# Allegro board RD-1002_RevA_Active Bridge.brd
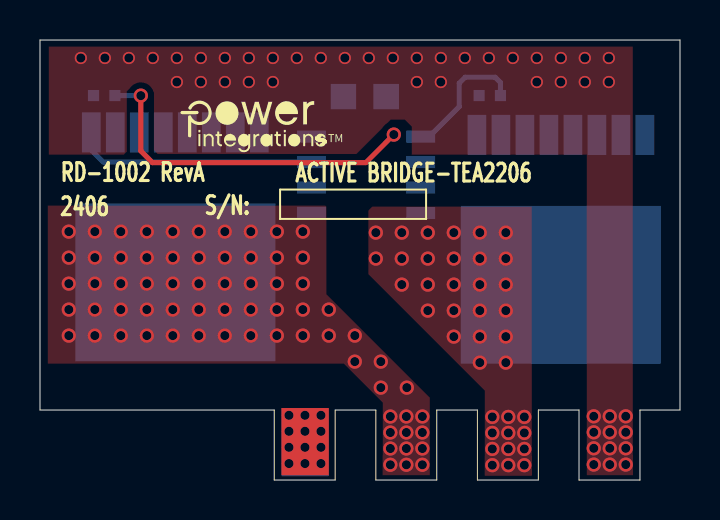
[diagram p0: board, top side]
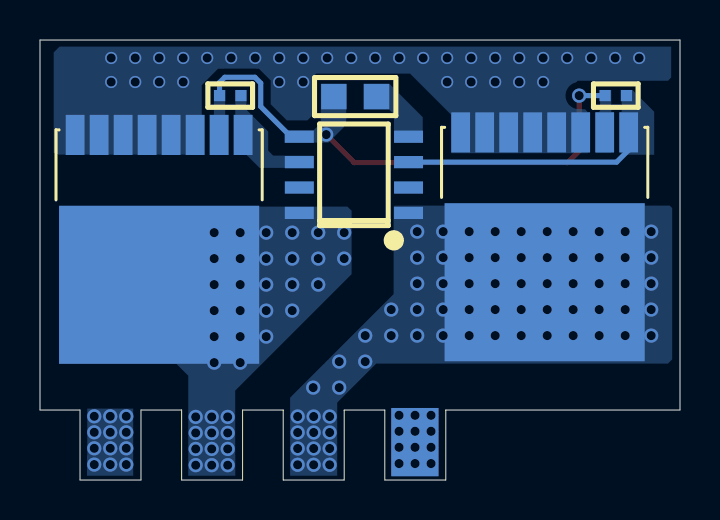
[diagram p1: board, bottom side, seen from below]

Outline 32 x 22 mm; copper layers: TOP, BOTTOM. Coordinates in mm from the lower left corner of the outline.
Outline path: 0,22 0,3.5 11.71,3.5 11.71,0 14.76,0 14.76,3.5 16.79,3.5 16.79,0 19.84,0 19.84,3.5 21.87,3.5 21.87,0 24.92,0 24.92,3.5 26.95,3.5 26.95,0 30,0 30,3.5 32,3.5 32,22 0,22

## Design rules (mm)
constraint set DEFAULT: min track width 0.254

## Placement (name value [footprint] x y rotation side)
C200  2.2 uF  [PISMC0805]  15.17 19.17 0 bottom
NOREF  -  []  -185.96 73.45 0 top
NOREF#2  -  []  11.71 0 90 top
NOREF#3  -  []  -262.6 -141.28 0 top
NOREF#4  -  []  11.71 0 0 top
NOREF#5  -  []  0 22 0 top
NOREF#6  -  []  0 3.5 90 top
NOREF#7  -  []  6.47 18.86 0 top
Q200  TK055U60Z1,RQ  [8POWER_SFN]  6.77 12.24 0 bottom
Q201  TK055U60Z1,RQ  [8POWER_SFN]  26.05 12.11 0 bottom
R200  100.0 k  [PISMR0402]  2.68 19.22 0 bottom
R201  100.0 k  [PISMR0402]  21.96 19.22 0 bottom
U200  TEA2206T/1J  [PISMSO8]  13.57 13.35 90 bottom

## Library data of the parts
C200 = CAP NP: room: 4
Q200 Q201 = FET_N_GSSD_1_2_345678_9
R200 R201 = R: alternate symbols: (Unisem_RMCF0402UL,pismr0402_1)
U200 = TEA2206T_1J

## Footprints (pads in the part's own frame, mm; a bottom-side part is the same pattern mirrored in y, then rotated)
8POWER_SFN
  rect 0.94x2.007 smd: 1(-4.2,-5.144) 2(-3,-5.144) 3(-1.8,-5.144) 4(-0.6,-5.144) 5(0.6,-5.144) 6(1.8,-5.144) 7(3,-5.144) 8(4.2,-5.144)
  rect 10.008x7.899 smd: 9(0,2.349)
PISMC0805
  rect 1.27x1.27 smd: 1(0,0) 2(2.134,0)
PISMR0402
  rect 0.559x0.559 smd: 1(0,0) 2(1.067,0)
PISMSO8
  rect 0.61x1.448 smd: 1(0,0) 2(1.27,0) 3(2.54,0) 4(3.81,0) 5(3.81,5.461) 6(2.54,5.461) 7(1.27,5.461) 8(0,5.461)

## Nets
AC_L_BRIDGE: Q201.9 U200.8
AC_N_BRIDGE: Q200.9 U200.1
BR_DRV_RTN: C200.2 Q200.2 Q201.2 R200.2 R201.2 U200.5
BR_GATE_1: Q200.1 R200.1 U200.3
BR_GATE_2: Q201.1 R201.1 U200.6
BR_VCC: C200.1 U200.4
RTN_BRIDGE: Q200.3 Q200.4 Q200.5 Q200.6 Q200.7 Q200.8 Q201.3 Q201.4 Q201.5 Q201.6 Q201.7 Q201.8

Pads without a net: U200 2 7

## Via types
v1: diameter 0.711, hole 0.457, TOP to BOTTOM, 133 vias
v2: diameter 0.61, hole 0.457, TOP to BOTTOM, 34 vias

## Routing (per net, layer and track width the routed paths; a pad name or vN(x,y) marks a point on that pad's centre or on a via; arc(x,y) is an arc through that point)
AC_L_BRIDGE:
  vias: v1(16.79,12.37) v1(16.79,11.07) v1(18.09,12.37) v1(18.09,11.07) v1(18.09,9.77) v1(19.39,12.37) v1(19.39,11.07) v1(19.39,9.77) v1(19.39,8.47) v1(20.69,12.37) v1(20.69,11.07) v1(20.69,9.77) v1(20.69,8.47) v1(20.69,7.17) v1(21.99,12.37) v1(21.99,11.07) v1(21.99,9.77) v1(21.99,8.47) v1(21.99,7.17) v1(21.99,5.87) v1(22.62,3.15) v1(22.62,2.35) v1(22.62,1.55) v1(22.62,0.74) v1(23.29,12.37) v1(23.29,11.07) v1(23.29,9.77) v1(23.29,8.47) v1(23.29,7.17) v1(23.29,5.87) v1(23.42,3.15) v1(23.42,2.35) v1(23.42,1.55) v1(23.42,0.74) v1(24.22,3.15) v1(24.22,2.35) v1(24.22,1.55) v1(24.22,0.74)
AC_N_BRIDGE:
  vias: v1(1.44,12.42) v1(1.44,11.12) v1(1.44,9.82) v1(1.44,8.52) v1(1.44,7.22) v1(2.74,12.42) v1(2.74,11.12) v1(2.74,9.82) v1(2.74,8.52) v1(2.74,7.22) v1(4.04,12.42) v1(4.04,11.12) v1(4.04,9.82) v1(4.04,8.52) v1(4.04,7.22) v1(5.34,12.42) v1(5.34,11.12) v1(5.34,9.82) v1(5.34,8.52) v1(5.34,7.22) v1(6.64,12.42) v1(6.64,11.12) v1(6.64,9.82) v1(6.64,8.52) v1(6.64,7.22) v1(7.94,12.42) v1(7.94,11.12) v1(7.94,9.82) v1(7.94,8.52) v1(7.94,7.22) v1(9.24,12.42) v1(9.24,11.12) v1(9.24,9.82) v1(9.24,8.52) v1(9.24,7.22) v1(10.54,12.42) v1(10.54,11.12) v1(10.54,9.82) v1(10.54,8.52) v1(10.54,7.22) v1(11.84,12.42) v1(11.84,11.12) v1(11.84,9.82) v1(11.84,8.52) v1(11.84,7.22) v1(13.14,12.42) v1(13.14,11.12) v1(13.14,9.82) v1(13.14,8.52) v1(13.14,7.22) v1(14.44,8.52) v1(14.44,7.22) v1(15.74,7.22) v1(15.74,5.92) v1(17.04,5.92) v1(17.04,4.62) v1(17.52,3.17) v1(17.52,2.37) v1(17.52,1.57) v1(17.52,0.76) v1(18.34,4.62) v1(18.32,3.17) v1(18.32,2.37) v1(18.32,1.57) v1(18.32,0.76) v1(19.12,3.17) v1(19.12,2.37) v1(19.12,1.57) v1(19.12,0.76)
BR_DRV_RTN: length 23.8
  TOP w0.249: 16.29,15.87 v1(17.69,17.27)
  TOP w0.254: 16.29,15.87 5.62,15.87 5.04,16.46 v1(5.04,19.22)
  BOTTOM w0.254: R200.2 5.04,19.22 v1(5.04,19.22) ; 23.02,19.22 R201.2 23.02,19.88 22.76,20.14 21.25,20.14 20.97,19.84 20.97,18.67 19.47,17.18
BR_GATE_1: length 12.1
  BOTTOM w0.254: U200.3 3.17,15.89 2.57,16.5 Q200.1
Net_85:
  vias: v1(12.45,3.24) v1(12.45,2.44) v1(12.45,1.63) v1(12.45,0.82) v1(13.25,3.24) v1(13.25,2.44) v1(13.25,1.63) v1(13.25,0.82) v1(14.05,3.24) v1(14.05,2.44) v1(14.05,1.63) v1(14.05,0.82)
RTN_BRIDGE:
  vias: v1(27.69,3.18) v1(27.69,2.38) v1(27.69,1.58) v1(27.69,0.77) v1(28.49,3.18) v1(28.49,2.38) v1(28.49,1.58) v1(28.49,0.77) v1(29.29,3.18) v1(29.29,2.38) v1(29.29,1.58) v1(29.29,0.77) v2(2.04,21.1) v2(3.24,21.1) v2(4.44,21.1) v2(5.64,21.1) v2(6.84,21.1) v2(6.84,19.9) v2(8.04,21.1) v2(8.04,19.9) v2(9.24,21.1) v2(9.24,19.9) v2(10.44,21.1) v2(10.44,19.9) v2(11.64,21.1) v2(11.64,19.9) v2(12.84,21.1) v2(14.04,21.1) v2(15.24,21.1) v2(16.44,21.1) v2(17.64,21.1) v2(18.84,21.1) v2(18.84,19.9) v2(20.04,21.1) v2(20.04,19.9) v2(21.24,21.1) v2(22.44,21.1) v2(23.64,21.1) v2(24.84,21.1) v2(24.84,19.9) v2(26.04,21.1) v2(26.04,19.9) v2(27.24,21.1) v2(27.24,19.9) v2(28.44,21.1) v2(28.44,19.9)

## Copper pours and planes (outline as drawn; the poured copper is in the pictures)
AC_L_BRIDGE on TOP: 24.59,1.22 24.59,13.67 16.62,13.67 16.62,13.67 16.42,13.47 16.42,10.29 22.24,4.47 22.24,1.22 22.24,1.22 22.24,0.21 24.6,0.21 24.6,1.21
AC_L_BRIDGE on BOTTOM: 24.59,5.22 25.19,5.82 30.99,5.82 31.04,5.77 31.04,13.67 16.63,13.67 16.48,13.52 16.47,13.52 16.42,13.46 16.42,10.29 22.24,4.47 22.24,1.22 22.24,1.22 22.24,0.21 24.6,0.21 24.59,0.22
AC_N_BRIDGE on TOP: 19.49,4.12 14.32,9.29 14.32,13.67 14.27,13.72 0.39,13.72 0.39,5.82 15.19,5.82 16.99,4.02 17.14,3.87 17.14,1.22 17.13,1.21 17.13,0.24 19.49,0.24 19.49,0.24
AC_N_BRIDGE on BOTTOM: 17.14,3.87 16.84,4.17 15.19,5.82 0.6,5.82 0.39,6.03 0.39,13.6 0.48,13.68 0.51,13.72 13.65,13.72 13.65,13.72 14.27,13.72 14.32,13.67 14.32,9.29 19.49,4.12 19.49,0.21 17.13,0.21 17.14,0.22
BR_DRV_RTN on BOTTOM: 22.74,19.5 22.74,16.32 23.3,16.32 23.3,19.5
BR_DRV_RTN on BOTTOM: 3.44,19.5 3.44,16.35 4.19,16.35 4.19,18.26 4,18.46 4,19.5 3.44,19.5
BR_DRV_RTN on BOTTOM: 16.69,17.76 17.58,16.87 19.77,16.87 19.78,16.87 19.78,17.49 19.77,17.49 18.32,17.49 17.96,17.85 17.96,19.81 16.69,19.81
BR_GATE_1 on BOTTOM: 1.29,16.27 2.92,16.27 2.92,19.5 2.38,19.5 1.29,18.42 1.29,16.27
BR_GATE_2 on BOTTOM: 18.32,16.22 20.34,16.22 20.59,16.47 20.59,17.43 21.68,18.51 21.68,19.48 21.69,19.5 22.23,19.5 22.24,19.49 22.24,16.26 22.24,16.25 21.67,16.25 21.02,15.6 18.33,15.6 18.32,15.61
BR_VCC on BOTTOM: 15.82,19.81 14.53,19.81 12.87,18.15 12.87,16.89 12.86,16.89 12.88,16.87 14.3,16.87 14.3,18.28 14.55,18.54 15.83,18.54 15.83,19.81
Net_84 on BOTTOM (solid shape): 14.44,0.19 12.08,0.19 12.08,3.6 14.44,3.6
Net_85 on TOP (solid shape): 14.44,0.24 12.08,0.24 12.08,3.6 14.44,3.6
RTN_BRIDGE on TOP: 29.64,1.25 29.65,1.24 29.65,0.24 27.34,0.24 27.34,16.27 18.59,16.27 18.59,17.67 18.24,18.02 17.54,18.02 15.79,16.27 5.91,16.27 5.7,16.48 5.7,19.38 5.3,19.78 4.7,19.78 4.34,19.43 4.34,16.42 4.19,16.27 0.44,16.27 0.44,21.67 29.64,21.67
RTN_BRIDGE on BOTTOM: 27.34,3.57 29.64,3.57 29.64,1.22 29.65,1.21 29.65,0.21 27.34,0.21
RTN_BRIDGE on BOTTOM: 0.44,21.67 31.02,21.67 31.32,21.38 31.32,16.36 31.23,16.27 24.04,16.27 23.91,16.4 23.91,19.75 23.84,19.82 23.29,20.37 23.1,20.56 21.05,20.56 20.46,19.98 20.46,18.78 19.66,17.98 18.63,17.98 18.39,18.22 18.39,20.12 18.19,20.32 13.5,20.32 11.44,18.26 11.44,16.37 11.41,16.34 4.61,16.34 4.61,18.39 4.75,18.54 5.04,18.54 5.52,18.74 5.72,19.22 5.57,19.64 5.19,19.88 5.12,19.96 0.61,19.96 0.44,20.12

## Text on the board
Ref Des/Silkscreen Top: 2406 | RD-1002 RevA | S/N: | ACTIVE BRIDGE-TEA2206
User.6: 14.  FAB HOUSE LOGO,DATE CODE TO BE IN SILK SCREEN ONLY.DO NOT USE COPPER. | 13.  MATERIAL FR4 COPPER 2oz THICKNESS 0.03"
User.8: FIGURE | FINISHED_SIZE | 18.0 | DRILL CHART: TOP to BOTTOM | ALL UNITS ARE IN MILS | TOLERANCE_DRILL | +3.0/-3.0 | PLATED | QTY | 167 | TOTAL HOLES:
